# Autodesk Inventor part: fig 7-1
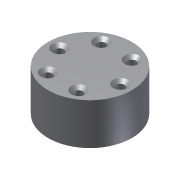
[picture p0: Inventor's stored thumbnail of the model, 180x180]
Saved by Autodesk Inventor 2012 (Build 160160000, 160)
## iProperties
Created: 2004-05
Part Number: fig 7-1
Document SubType Name: Modeling
Designer: CADCIM Technologies
Manufacturer: Standard
Standards Organization: Custom
Density: 1 g/cm^3
Material: Default
Author: CADCIM Technologies
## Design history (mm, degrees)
sketch "Sketch1"
  geometry: C1 r 17.175 at (0, 0)
  constraints: 1 centre point
extrude "Extrusion1" new body sketch "Sketch1" distance "d0" = 17; taper "d1" = 0 deg
sketch "Sketch2"
  geometry: 1 further point
hole "Hole1" sketch "Sketch2" at (12.571, -0.074) diameter "d2" = 3.5; stored, may be unused: countersink angle "d6" = 90 deg, drill point angle "d8" = 118 deg; dims "d3" = 6, "d4" = 6, "d5" = 2, "d7" = 8
pattern_circular "Circular Pattern1" dims angle "d11" = 360 deg
body "Solid1"
